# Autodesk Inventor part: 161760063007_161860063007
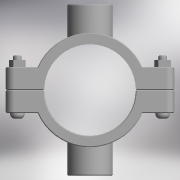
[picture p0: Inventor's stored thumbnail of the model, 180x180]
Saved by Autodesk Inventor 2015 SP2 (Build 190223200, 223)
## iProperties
Created: 2017-05
Part Number: 161760063007_161860063007
Material: Generic
Description: PLASSON DOUBLE SADDLE 63-3/4"
Document SubType Name: Modeling
Designer: KIM
Density: 1 g/cm^3
Appearance: Default
Author: KIM
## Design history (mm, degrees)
derived "16176.ipt"
feature "Solid1::16176.ipt"
feature "Solid2::16176.ipt"
tag "TaggingFeature1"
body "Solid1"
body "Solid2"
other parameters: "d0" = 78.75, "d1" = 116, "d2" = 31.5, "d3" = 63, "d4" = 84, "d5" = 0, "d6" = 5.8, "d7" = 116, "d8" = 0.1, "d10" = 0, "d11" = 0.63, "d20" = 0.63, "d23" = 0.63, "d37" = 8, "d38" = 39.5, "d39" = 0, "d40" = 3, "d41" = 5, "d42" = 0, "d43" = 6, "d44" = 3, "d45" = 0, "d46" = 0.63, "d52" = 24.117, "d53" = 19, "d54" = 0, "d57" = 0, "d58" = 68.04, "d60" = 0, "d63" = 8, "d66" = 68, "d67" = 118, "d68" = 31.3521, "d69" = 24.117, "d70" = 19, "d71" = 0, "d74" = 0, "d75" = 0.63, "d_" = 63, "G_" = 24.117, "A_" = 59, "L_" = 116, "L_1" = 84, "l_2" = 19
